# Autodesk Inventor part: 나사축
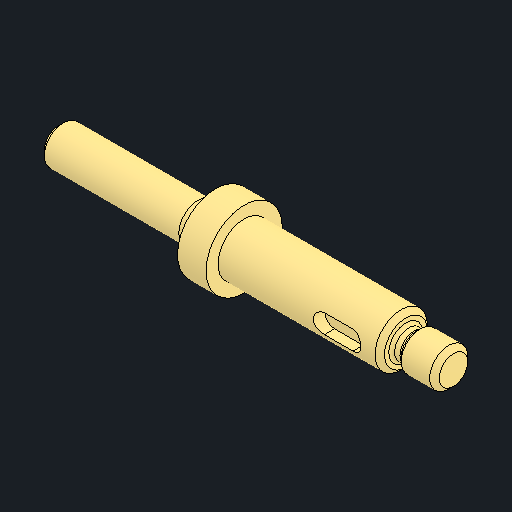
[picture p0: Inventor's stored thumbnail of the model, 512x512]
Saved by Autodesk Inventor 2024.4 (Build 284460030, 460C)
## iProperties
Created: 2026-08
Part Number: 나사축
Material: 강철, 탄소
Document SubType Name: Modeling
Designer: user
Density: 7.85 g/cm^3
Appearance: 기본값
Author: jhkim
Sending System: Autodesk Inventor 2027
Preprocessor: ST-DEVELOPER v20.1
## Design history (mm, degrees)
feature "솔리드1"
node "솔리드2"
